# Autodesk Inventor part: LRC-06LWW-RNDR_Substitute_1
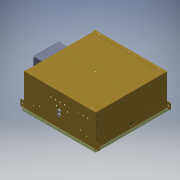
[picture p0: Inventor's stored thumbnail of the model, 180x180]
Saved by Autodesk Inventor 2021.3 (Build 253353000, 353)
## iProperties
Part Number: LRC-06LWW-RNDR_Substitute_1
Material: Generic
Document SubType Name: Modeling
Designer: JChurch
Manufacturer: Standard
Standards Organization: Custom
Density: 1 g/cm^3
Appearance: Smooth - Black
Author: JChurch
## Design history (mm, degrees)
derived "LRC-06LWW-RNDR.iam"
body "Solid9"
node "830399-00-00.ipt:1"
node "881088-00-00.iam:1::830140-00-00.ipt:1"
body "Solid10"
node "881088-00-00.iam:1::850014-00-00.iam:1::805044-00-00.ipt:1"
body "Solid11"
node "881088-00-00.iam:1::850014-00-00.iam:1::805174-00-00.ipt:1"
body "Solid12"
node "881088-00-00.iam:1::850014-00-00.iam:1::502055-00-00.ipt:1"
body "Solid13"
node "881088-00-00.iam:1::850014-00-00.iam:1::502055-00-00.ipt:2"
body "Solid14"
node "881088-00-00.iam:1::850014-00-00.iam:1::507032-00-00.ipt:1"
body "Solid15"
node "881088-00-00.iam:1::507000-00-00.ipt:1"
body "Solid16"
node "881088-00-00.iam:1::507000-00-00.ipt:2"
body "Solid17"
node "881088-00-00.iam:1::506002-00-00.ipt:1"
body "Solid18"
node "881088-00-00.iam:1::506002-00-00.ipt:2"
body "Solid19"
node "881088-00-00.iam:1::506002-00-00.ipt:3"
body "Solid20"
node "881088-00-00.iam:1::506002-00-00.ipt:4"
body "Solid21"
node "881088-00-00.iam:1::506002-00-00.ipt:5"
body "Solid22"
node "881088-00-00.iam:1::506002-00-00.ipt:6"
body "Solid23"
node "881088-00-00.iam:1::506002-00-00.ipt:7"
body "Solid24"
node "881088-00-00.iam:1::506002-00-00.ipt:8"
body "Solid25"
node "881088-00-00.iam:1::506002-00-00.ipt:9"
body "Solid26"
node "881088-00-00.iam:1::506002-00-00.ipt:10"
body "Solid27"
node "881088-00-00.iam:1::506002-00-00.ipt:11"
body "Solid28"
node "881088-00-00.iam:1::506002-00-00.ipt:12"
body "Solid29"
node "881088-00-00.iam:1::506002-00-00.ipt:13"
body "Solid30"
node "881088-00-00.iam:1::506002-00-00.ipt:14"
body "Solid31"
node "881088-00-00.iam:1::830392-01-00.iam:1::830392-00-00.ipt:1"
body "Solid32"
node "881088-00-00.iam:1::830392-01-00.iam:1::500027-00-00.ipt:1"
body "Solid33"
node "881088-00-00.iam:1::830392-01-00.iam:1::501030-00-00.ipt:1"
body "Solid34"
node "881088-00-00.iam:1::830392-01-00.iam:1::500027-00-00.ipt:2"
body "Solid35"
node "881088-00-00.iam:1::830392-01-00.iam:1::501030-00-00.ipt:2"
body "Solid36"
node "881088-00-00.iam:1::830392-01-00.iam:1::501030-00-00.ipt:3"
body "Solid37"
node "881088-00-00.iam:1::830392-01-00.iam:1::501030-00-00.ipt:4"
body "Solid38"
node "881088-00-00.iam:1::830392-01-00.iam:2::830392-00-00.ipt:1"
body "Solid39"
node "881088-00-00.iam:1::830392-01-00.iam:2::500027-00-00.ipt:1"
body "Solid40"
node "881088-00-00.iam:1::830392-01-00.iam:2::501030-00-00.ipt:1"
body "Solid41"
node "881088-00-00.iam:1::830392-01-00.iam:2::500027-00-00.ipt:2"
body "Solid42"
node "881088-00-00.iam:1::830392-01-00.iam:2::501030-00-00.ipt:2"
body "Solid43"
node "881088-00-00.iam:1::830392-01-00.iam:2::501030-00-00.ipt:3"
body "Solid44"
node "881088-00-00.iam:1::830392-01-00.iam:2::501030-00-00.ipt:4"
body "Solid45"
node "700458-00-XX.iam:1::710139-00-00.ipt:1"
body "Solid46"
node "700458-00-XX.iam:1::700452-01-00.ipt:1"
body "Solid47"
node "700458-00-XX.iam:1::510048-00-00_5.72 DIA..ipt:1"
body "Solid48"
node "725075-02-00.ipt:1"
body "Solid49"
other parameters: "d15" = 61.595, "d16" = 9.525, "d17" = 9.525, "d35" = 5.08
